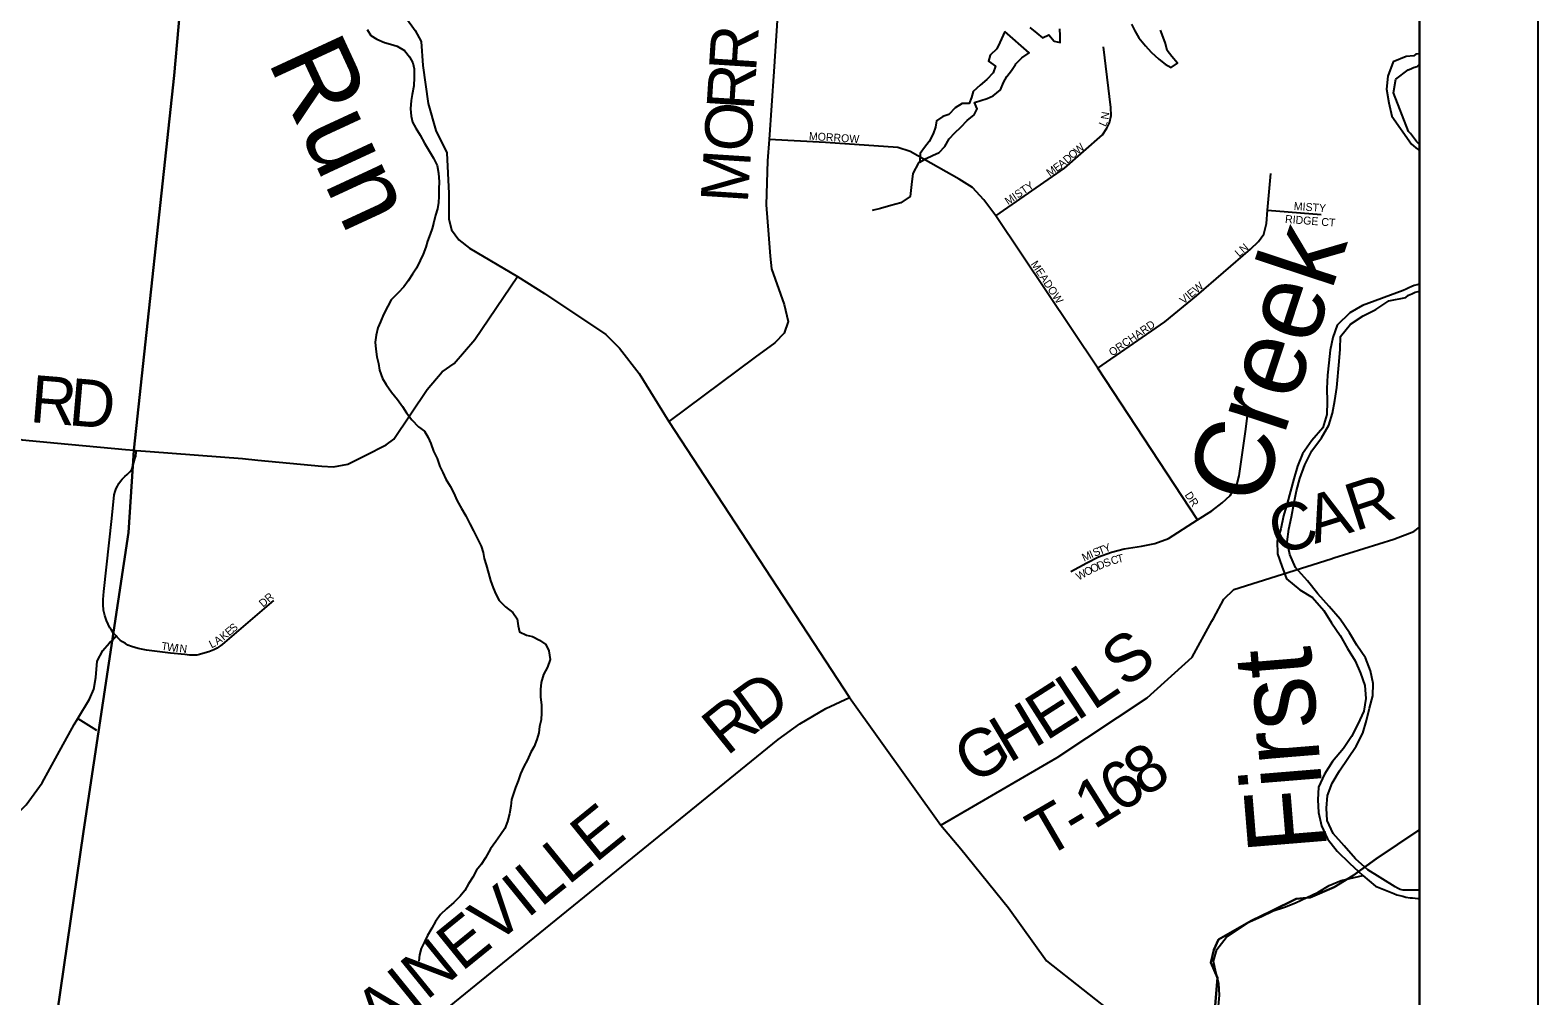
# Model space of a CAD drawing. Extents: x 0 to 34, y -4 to 22.
# Drawn here: x 7.725 to 9, y 14.851 to 15.668 of the extents above; entities that cross this region are included whole.
import ezdxf

# ---------------------------------------------------------------- set-up
doc = ezdxf.new("R2010")
doc.units = 0
for name, color, linetype in [('GM_X_County_Road', 7, 'Continuous'), ('GM_X_County_Road_Text', 7, 'Continuous'), ('GM_X_Minor_Lake', 7, 'Continuous'), ('GM_X_Minor_River', 7, 'Continuous'), ('GM_X_Minor_River_Text', 7, 'Continuous'), ('GM_X_Township', 7, 'Continuous'), ('GM_X_Township_Road', 7, 'Continuous'), ('GM_X_Township_Road_Text', 7, 'Continuous'), ('GM_X_Township_Subdivision', 7, 'Continuous'), ('GM_X_Township_Subdivision_Text', 7, 'Continuous'), ('SH_Data', 7, 'Continuous'), ('SN_P_Text', 7, 'Continuous')]:
    doc.layers.add(name, color=color, linetype=linetype)

msp = doc.modelspace()

# ---------------------------------------------------------------- linework, layer by layer
at = {"layer": 'GM_X_County_Road'}
for points in [[(8.0173, 15.7141), (8.0505, 15.668), (8.0555, 15.6587), (8.057, 15.6384), (8.0615, 15.6063), (8.0679, 15.5834), (8.0771, 15.5644), (8.079, 15.5301), (8.0789, 15.5087), (8.0811, 15.4993), (8.0874, 15.4908), (8.0965, 15.4837), (8.137, 15.46), (8.1598, 15.4455), (8.2116, 15.4109), (8.2233, 15.3992), (8.2398, 15.3777), (8.2649, 15.3373)], [(8.3588, 15.711), (8.3537, 15.6333), (8.3498, 15.5756), (8.3485, 15.5576), (8.3474, 15.5205), (8.3493, 15.4955), (8.3507, 15.4772), (8.3518, 15.4663), (8.3625, 15.4361), (8.366, 15.4219), (8.3625, 15.412), (8.3547, 15.4037), (8.3379, 15.3917), (8.2649, 15.3373)], [(8.2649, 15.3373), (8.4177, 15.1037), (8.4949, 14.9957), (8.5119, 14.9757), (8.5524, 14.9258), (8.5844, 14.8809), (8.6458, 14.8325), (8.7276, 14.7769)], [(7.7213, 14.589), (7.7418, 14.5871), (7.7622, 14.5878), (7.773, 14.5936), (8.3575, 15.0682), (8.3759, 15.0816), (8.3979, 15.0945), (8.4177, 15.1037)]]:
    msp.add_lwpolyline(points, dxfattribs=at)
at = {"layer": 'GM_X_Minor_Lake'}
for points in [[(8.6562, 15.6733), (8.6591, 15.6676), (8.6624, 15.6617), (8.6682, 15.6549), (8.6729, 15.6495), (8.6793, 15.6438), (8.6848, 15.6394), (8.6898, 15.6366), (8.6953, 15.6403), (8.6903, 15.646), (8.6866, 15.6511), (8.6851, 15.6568), (8.6831, 15.6624), (8.6807, 15.6683)], [(8.5491, 15.6672), (8.545, 15.6577), (8.5425, 15.6524), (8.5367, 15.6471), (8.5353, 15.642), (8.5414, 15.6377), (8.5392, 15.6321), (8.534, 15.6266), (8.5283, 15.6218), (8.5223, 15.6163), (8.5209, 15.6113), (8.5189, 15.6062), (8.5131, 15.6063), (8.5071, 15.6024), (8.5019, 15.5969), (8.4968, 15.5951), (8.4914, 15.5914), (8.4905, 15.5861), (8.4886, 15.5805), (8.4852, 15.5741), (8.4811, 15.5691), (8.4776, 15.5638), (8.4772, 15.5566), (8.4826, 15.5597), (8.488, 15.5623), (8.4936, 15.5647), (8.4985, 15.5699), (8.5021, 15.5763), (8.5068, 15.5813), (8.5119, 15.5863), (8.5174, 15.5918), (8.5233, 15.5965), (8.5258, 15.6018), (8.5235, 15.6069), (8.5289, 15.6087), (8.5343, 15.6103), (8.5394, 15.6126), (8.5454, 15.6178), (8.5481, 15.6239), (8.5509, 15.629), (8.5547, 15.634), (8.5583, 15.6393), (8.5586, 15.6396)], [(8.5586, 15.6396), (8.5635, 15.6448), (8.5697, 15.649), (8.5491, 15.6672)], [(8.5703, 15.6706), (8.5761, 15.6657), (8.5811, 15.6616), (8.5865, 15.6642), (8.591, 15.6588), (8.596, 15.6577), (8.5961, 15.6635), (8.5957, 15.6694)]]:
    msp.add_lwpolyline(points, dxfattribs=at)
at = {"layer": 'GM_X_Minor_River'}
for points in [[(8.0099, 15.6689), (8.013, 15.6637), (8.0181, 15.6605), (8.0244, 15.6579), (8.0295, 15.6565), (8.0353, 15.6548), (8.0414, 15.651), (8.0456, 15.6458), (8.0485, 15.6407), (8.0495, 15.6354), (8.0496, 15.6281), (8.0492, 15.6212), (8.048, 15.6137), (8.0469, 15.6087), (8.0465, 15.6017), (8.0469, 15.5956), (8.0482, 15.5905), (8.051, 15.5853), (8.0547, 15.5794), (8.0583, 15.5727), (8.0617, 15.567), (8.0659, 15.56), (8.069, 15.5538), (8.0702, 15.5473), (8.0706, 15.5398), (8.0705, 15.534), (8.0704, 15.5276), (8.0701, 15.5225), (8.0692, 15.5171), (8.0677, 15.5118)], [(8.9, 15.6483), (8.8998, 15.6482), (8.8969, 15.648), (8.8951, 15.6465), (8.8885, 15.646)], [(8.8885, 15.646), (8.8777, 15.6414), (8.873, 15.6294), (8.872, 15.6182), (8.8739, 15.6067), (8.8764, 15.5954), (8.893, 15.5718)], [(8.8906, 15.5826), (8.8778, 15.6152), (8.8799, 15.6269), (8.8903, 15.6348)], [(8.8903, 15.6348), (8.8925, 15.6355), (8.8949, 15.6365), (8.8979, 15.6375), (8.9, 15.6395)], [(8.9, 15.5714), (8.8997, 15.5717), (8.8974, 15.5741), (8.8956, 15.5763), (8.894, 15.5785), (8.8922, 15.5807), (8.8906, 15.5826)], [(8.893, 15.5718), (8.8949, 15.5705), (8.8967, 15.5688), (8.8988, 15.5674), (8.9, 15.5665)], [(8.4772, 15.5566), (8.476, 15.5559), (8.4714, 15.5469), (8.4701, 15.5376), (8.4691, 15.5275), (8.4612, 15.5223), (8.4528, 15.5198), (8.4439, 15.5174), (8.4369, 15.5157)], [(8.0677, 15.5118), (8.0663, 15.5057), (8.0649, 15.5006), (8.0632, 15.4956), (8.0609, 15.4897), (8.0595, 15.4847), (8.0573, 15.4788), (8.0545, 15.4733), (8.0515, 15.4669), (8.0482, 15.4619), (8.0446, 15.4563), (8.0408, 15.451), (8.0359, 15.446), (8.0302, 15.44), (8.0274, 15.4347), (8.0235, 15.4278), (8.021, 15.4214), (8.0188, 15.4164), (8.0174, 15.4102), (8.0167, 15.4044), (8.0172, 15.3985), (8.0181, 15.392), (8.0194, 15.3864), (8.0201, 15.3805), (8.0229, 15.3735), (8.0258, 15.3684), (8.0305, 15.3619), (8.0355, 15.3557), (8.0396, 15.35), (8.043, 15.3446), (8.0477, 15.3386), (8.0533, 15.3327), (8.0583, 15.3291), (8.0614, 15.3237), (8.0637, 15.3186), (8.066, 15.3121), (8.0689, 15.3059), (8.0714, 15.2992), (8.0738, 15.2941), (8.0763, 15.2885), (8.08, 15.2825), (8.0828, 15.2771), (8.0859, 15.2701), (8.0896, 15.2636), (8.0932, 15.2574), (8.0966, 15.2507), (8.0997, 15.2448), (8.1038, 15.2369), (8.1062, 15.2318), (8.1079, 15.2265), (8.1089, 15.2214), (8.1104, 15.216), (8.1125, 15.209), (8.1142, 15.2028), (8.1163, 15.1966), (8.1186, 15.1913), (8.1214, 15.1859), (8.1267, 15.1804), (8.1331, 15.1758), (8.1367, 15.1704), (8.1374, 15.1645), (8.1387, 15.1594), (8.1445, 15.1566), (8.1496, 15.1555), (8.1557, 15.1522), (8.161, 15.1486), (8.1635, 15.1432), (8.1645, 15.136), (8.1622, 15.1293), (8.1589, 15.1232), (8.157, 15.1166), (8.1563, 15.1105), (8.1565, 15.104), (8.1574, 15.0976), (8.1573, 15.0907), (8.157, 15.085), (8.1555, 15.0792), (8.1549, 15.0739), (8.1532, 15.0683), (8.151, 15.0624), (8.1482, 15.0574), (8.1454, 15.051), (8.1424, 15.0454), (8.1394, 15.0391), (8.1374, 15.0332), (8.1352, 15.0276), (8.1337, 15.0226), (8.132, 15.0175), (8.1312, 15.0119), (8.1302, 15.0053), (8.1285, 14.9989), (8.1263, 14.993), (8.1225, 14.9877), (8.1186, 14.9819), (8.114, 14.9758), (8.1098, 14.9682), (8.1063, 14.9626), (8.1024, 14.9576), (8.0991, 14.9518), (8.0956, 14.9462), (8.0923, 14.9406)], [(8.8862, 15.4481), (8.8518, 15.4354), (8.841, 15.4292), (8.8304, 15.4187), (8.8267, 15.4083), (8.8244, 15.3976), (8.8232, 15.3867), (8.8222, 15.3763), (8.8215, 15.3651), (8.8218, 15.3541), (8.8214, 15.3431), (8.818, 15.332), (8.8087, 15.3212), (8.8008, 15.3098), (8.7966, 15.2994), (8.7935, 15.2888), (8.7909, 15.2784), (8.788, 15.268), (8.7849, 15.2574), (8.7826, 15.2464), (8.7795, 15.2361), (8.7798, 15.2254), (8.7834, 15.2149), (8.7875, 15.2041), (8.7986, 15.1949), (8.8095, 15.1883), (8.8189, 15.1774), (8.8254, 15.1669), (8.8327, 15.1561), (8.839, 15.1453), (8.8455, 15.1348), (8.8499, 15.1243), (8.8537, 15.1138), (8.8546, 15.1028), (8.8528, 15.0921), (8.8478, 15.0813), (8.8423, 15.0709), (8.8357, 15.0606), (8.8264, 15.0495), (8.8196, 15.0389), (8.8146, 15.028), (8.8139, 15.0171), (8.8145, 15.0064), (8.817, 14.9951), (8.8222, 14.9843), (8.8303, 14.9738), (8.8408, 14.9637), (8.8521, 14.9531), (8.8627, 14.9441), (8.8781, 14.9379)], [(8.9, 15.4534), (8.8978, 15.4529), (8.8954, 15.4522), (8.8935, 15.4514), (8.8908, 15.4502), (8.8886, 15.4492), (8.8862, 15.4481)], [(8.8882, 15.4422), (8.8907, 15.444), (8.8934, 15.4453), (8.8963, 15.4466), (8.8988, 15.4473), (8.9, 15.4474)], [(8.8793, 14.9437), (8.8562, 14.9579), (8.8457, 14.9674), (8.8362, 14.9782), (8.827, 14.9888), (8.8219, 14.9996), (8.8212, 15.0103), (8.8222, 15.021), (8.8261, 15.0313), (8.8322, 15.0417), (8.8393, 15.0522), (8.8462, 15.0626), (8.852, 15.0737), (8.8551, 15.0843), (8.8577, 15.0947), (8.8605, 15.1051), (8.8607, 15.1155), (8.8585, 15.1263), (8.8541, 15.1373), (8.847, 15.1481), (8.8408, 15.1586), (8.8327, 15.17), (8.8235, 15.1808), (8.8138, 15.1914), (8.8051, 15.2025), (8.7949, 15.2136), (8.7903, 15.2247), (8.788, 15.2354), (8.7893, 15.2461), (8.7916, 15.2565), (8.7936, 15.2674), (8.796, 15.2786), (8.7988, 15.289), (8.803, 15.3007), (8.8088, 15.3123), (8.817, 15.3234), (8.8231, 15.334), (8.8262, 15.3444), (8.8283, 15.3551), (8.8301, 15.366), (8.832, 15.3879), (8.8327, 15.3983), (8.8332, 15.409), (8.8414, 15.4196), (8.8522, 15.4266), (8.863, 15.432), (8.8741, 15.4394), (8.8882, 15.4422)], [(8.7299, 14.8428), (8.7306, 14.8521), (8.7303, 14.862), (8.7275, 14.8714), (8.7258, 14.8808), (8.7286, 14.8907), (8.7365, 14.9007), (8.7465, 14.9075), (8.7568, 14.9143), (8.7662, 14.9184), (8.7762, 14.9233), (8.7856, 14.9264), (8.795, 14.93), (8.8047, 14.9346), (8.8142, 14.939), (8.8236, 14.9448), (8.8336, 14.9489), (8.8521, 14.9531)], [(8.0923, 14.9406), (8.0884, 14.9356), (8.083, 14.9304), (8.077, 14.9251), (8.0719, 14.9201), (8.0675, 14.9143), (8.0645, 14.9087), (8.0609, 14.9024), (8.0584, 14.8971), (8.0556, 14.8915), (8.0542, 14.8862), (8.0536, 14.8808)], [(8.8781, 14.9379), (8.8808, 14.9368), (8.8834, 14.9362), (8.8858, 14.9356), (8.8882, 14.935), (8.892, 14.9343), (8.8941, 14.9343), (8.8963, 14.934), (8.8984, 14.9337), (8.9, 14.9335)], [(8.9, 14.9408), (8.8988, 14.9409), (8.8967, 14.9407), (8.8948, 14.9407), (8.8929, 14.9407), (8.8908, 14.9408), (8.8887, 14.9408), (8.886, 14.9409), (8.8836, 14.9415), (8.8812, 14.9426), (8.8793, 14.9437)]]:
    msp.add_lwpolyline(points, dxfattribs=at)
at = {"layer": 'GM_X_Township'}
for points in [[(8.7269, 14.8398), (8.729, 14.8668), (8.7233, 14.8795), (8.726, 14.8904), (8.7299, 14.8992), (8.7574, 14.9149), (8.7743, 14.9231), (8.7955, 14.9334), (8.8073, 14.9346), (8.8276, 14.9434), (8.8439, 14.9533), (8.8632, 14.9673), (8.8993, 14.9917), (8.9, 14.9923), (8.9, 19.071)], [(3.8794, 14.1), (7.6703, 14.1), (7.7118, 14.5899), (7.7699, 14.9905), (7.8078, 15.2433), (7.8116, 15.2993), (7.8125, 15.3129), (7.8465, 15.6298), (7.8833, 16.0418)], [(7.8833, 16.0418), (7.8465, 15.6298), (7.8125, 15.3129), (7.8116, 15.2993), (7.8078, 15.2433), (7.7699, 14.9905), (7.7118, 14.5899)], [(8.9, 14.1), (8.9, 14.9923), (8.8993, 14.9917), (8.8632, 14.9673), (8.8439, 14.9533), (8.8276, 14.9434), (8.8073, 14.9346), (8.7955, 14.9334), (8.7743, 14.9231), (8.7574, 14.9149), (8.7299, 14.8992), (8.726, 14.8904), (8.7233, 14.8795), (8.729, 14.8668), (8.7269, 14.8398)]]:
    msp.add_lwpolyline(points, dxfattribs=at)
at = {"layer": 'GM_X_Township_Road'}
for points in [[(7.9172, 15.3046), (7.9715, 15.2994), (7.9813, 15.299), (7.9934, 15.3012), (8.0081, 15.3086), (8.0259, 15.3175), (8.0323, 15.3224), (8.0606, 15.3642), (8.0732, 15.3791), (8.0834, 15.3863), (8.1009, 15.4065), (8.137, 15.46)], [(7.248, 15.4237), (7.3198, 15.4102), (7.4966, 15.373), (7.6114, 15.3461), (7.6877, 15.3284), (7.7181, 15.3218), (7.7478, 15.3188), (7.8053, 15.3135)], [(7.8053, 15.3135), (7.8125, 15.3129), (7.8143, 15.3128), (7.8263, 15.3119)], [(7.8263, 15.3119), (7.9044, 15.3058), (7.9172, 15.3046)], [(8.8275, 15.2218), (8.8782, 15.2377), (8.8951, 15.2443), (8.9, 15.2478)], [(8.7256, 15.1707), (8.7345, 15.1869), (8.7429, 15.195), (8.8253, 15.221), (8.8275, 15.2218)], [(8.4949, 14.9957), (8.5933, 15.0529), (8.6696, 15.1034), (8.7076, 15.138), (8.7243, 15.1683), (8.7256, 15.1707)]]:
    msp.add_lwpolyline(points, dxfattribs=at)
at = {"layer": 'GM_X_Township_Subdivision'}
for points in [[(8.5415, 15.5113), (8.5996, 15.5515), (8.6317, 15.5797), (8.6354, 15.5853), (8.6378, 15.5899), (8.639, 15.596), (8.6388, 15.6028), (8.6325, 15.6541)], [(8.7122, 15.2541), (8.6279, 15.3823), (8.5415, 15.5113), (8.5314, 15.5247), (8.5218, 15.5351), (8.5106, 15.5422), (8.4692, 15.5656), (8.4588, 15.5689), (8.3974, 15.5731), (8.3498, 15.5756)], [(8.6279, 15.3823), (8.6845, 15.4216), (8.7113, 15.4435), (8.757, 15.4829), (8.7638, 15.4895), (8.7682, 15.4958), (8.7704, 15.5048), (8.7714, 15.5159), (8.7742, 15.5469)], [(8.7714, 15.5159), (8.8166, 15.5124)], [(8.605, 15.2103), (8.6186, 15.2178), (8.6283, 15.2227), (8.6395, 15.2266), (8.6502, 15.2295), (8.6648, 15.2319), (8.676, 15.2341), (8.6877, 15.2382), (8.7122, 15.2541), (8.7242, 15.2616), (8.7329, 15.2684), (8.7397, 15.2747), (8.7456, 15.2849), (8.7475, 15.2913), (8.7528, 15.3289), (8.7543, 15.3421)], [(7.8116, 15.2993), (7.8133, 15.3055), (7.814, 15.3079), (7.8143, 15.3113), (7.8143, 15.3128)], [(7.7951, 15.1584), (7.7933, 15.1613), (7.7922, 15.1628), (7.7906, 15.1658), (7.7892, 15.1689), (7.7879, 15.173), (7.7868, 15.1775), (7.7864, 15.1824), (7.7866, 15.1867), (7.7871, 15.1933), (7.7937, 15.2553), (7.7959, 15.2753), (7.7968, 15.278), (7.7976, 15.2805), (7.7986, 15.2826), (7.7998, 15.2847), (7.8013, 15.2867), (7.8027, 15.2884), (7.8049, 15.2906), (7.8068, 15.2925), (7.8091, 15.2947), (7.8107, 15.2967), (7.8116, 15.2993)], [(7.9306, 15.1858), (7.8873, 15.1487), (7.8859, 15.1477), (7.8844, 15.1466), (7.8828, 15.1454), (7.88, 15.144), (7.8759, 15.1424), (7.8727, 15.1415), (7.8679, 15.1401), (7.8656, 15.1397), (7.8632, 15.1397), (7.8596, 15.1397), (7.8556, 15.1401), (7.8434, 15.1414), (7.8231, 15.1439), (7.816, 15.1453), (7.8106, 15.1469), (7.8075, 15.148), (7.8053, 15.1494), (7.803, 15.1509), (7.801, 15.1523), (7.7983, 15.1549), (7.7975, 15.1559), (7.7966, 15.1568), (7.7951, 15.1584)], [(7.5588, 14.9904), (7.6124, 14.9886), (7.6672, 14.9875), (7.6799, 14.9899), (7.6943, 14.9939), (7.7121, 15.0035), (7.7214, 15.013), (7.735, 15.0317), (7.748, 15.0553), (7.7621, 15.0809), (7.7652, 15.086), (7.7749, 15.1024), (7.7786, 15.1107), (7.7802, 15.1208), (7.7815, 15.1346), (7.7861, 15.1435), (7.788, 15.1456), (7.7899, 15.1477), (7.792, 15.1501), (7.7941, 15.1519)], [(7.7941, 15.1519), (7.7975, 15.1559)], [(7.7652, 15.086), (7.781, 15.0761)]]:
    msp.add_lwpolyline(points, dxfattribs=at)
at = {"layer": 'SH_Data'}
for p, q in [((9, 21), (9, 14)), ((8.9, 20.9), (8.9, 14.1))]:
    msp.add_line(p, q, dxfattribs=at)
at = {"layer": 'SN_P_Text'}
msp.add_lwpolyline([(8.9, 14.1), (8.9, 20.9), (2.1, 20.9), (2.1, 14.1)], close=True, dxfattribs=at)

# ---------------------------------------------------------------- texts
at = {"layer": 'GM_X_County_Road_Text'}
for s, rotation, p in [('R', 86.3553, (8.3387, 15.6325)), ('R', 86.3521, (8.3367, 15.5997)), ('O', 86.3538, (8.3344, 15.5646)), ('M', 86.3527, (8.3317, 15.5212)), ('D', 36.3482, (8.3393, 15.074)), ('R', 38.8006, (8.3141, 15.0537)), ('FOSTERS-MAINEVILLE', 39.0783, (7.7761, 14.6166))]:
    msp.add_text(s, height=0.04, rotation=rotation, dxfattribs=at).set_placement(p)
at = {"layer": 'GM_X_Minor_River_Text'}
for s, rotation, p in [('Run', 294.8367, (7.9253, 15.6423)), ('Creek', 71.7417, (8.7649, 15.2633)), ('First', 94.6723, (8.8219, 14.9753))]:
    msp.add_text(s, height=0.06667, rotation=rotation, dxfattribs=at).set_placement(p)
at = {"layer": 'GM_X_Township_Road_Text'}
for s, rotation, p in [('R', 355.3699, (7.7238, 15.3368)), ('D', 355.08, (7.7565, 15.3342)), ('R', 17.9544, (8.8454, 15.2442)), ('A', 17.3586, (8.8114, 15.2336)), ('C', 17.3475, (8.78, 15.2238)), ('S', 38.3301, (8.6514, 15.111)), ('L', 33.8615, (8.6238, 15.0923)), ('E', 32.5812, (8.5841, 15.0666)), ('I', 33.4753, (8.6098, 15.0831)), ('H', 30.9121, (8.5528, 15.0478)), ('G', 30.2591, (8.5219, 15.0298)), ('8', 33.393, (8.6669, 15.0187)), ('6', 33.0544, (8.6461, 15.0051)), ('1', 32.0905, (8.6246, 14.9916)), ('T', 30.2185, (8.5834, 14.9673)), ('-', 31.1379, (8.6099, 14.9827))]:
    msp.add_text(s, height=0.04, rotation=rotation, dxfattribs=at).set_placement(p)
at = {"layer": 'GM_X_Township_Subdivision_Text'}
for s, rotation, p in [('N', 81.4249, (8.6368, 15.5923)), ('L', 66.0264, (8.6344, 15.5861)), ('MORROW', 356.4228, (8.3833, 15.5754)), ('W', 41.0736, (8.6109, 15.5627)), ('A', 38.7854, (8.5972, 15.5511)), ('D', 41.0022, (8.602, 15.555)), ('O', 41.0817, (8.6064, 15.5588)), ('M', 35.0592, (8.5872, 15.5441)), ('E', 35.0934, (8.593, 15.5481)), ('MISTY', 34.4414, (8.552, 15.52)), ('MISTY', 356.0112, (8.7934, 15.5162)), ('RIDGE CT', 355.5318, (8.786, 15.5053)), ('LN', 40.9166, (8.7473, 15.476)), ('MEADOW', 303.4764, (8.5708, 15.4704)), ('VIEW', 39.8086, (8.7004, 15.4361)), ('ORCHARD', 34.853, (8.64, 15.3921)), ('DR', 303.6867, (8.701, 15.2751)), ('M', 24.1696, (8.6162, 15.2186)), ('I', 24.14, (8.6226, 15.2215)), ('S', 22.603, (8.6252, 15.2227)), ('T', 20.5784, (8.6295, 15.2244)), ('Y', 21.0944, (8.634, 15.2261)), ('O', 27.9143, (8.6183, 15.2063)), ('O', 25.7734, (8.6234, 15.209)), ('D', 23.3966, (8.6286, 15.2115)), ('S', 20.7511, (8.634, 15.2138)), ('C', 16.1155, (8.6399, 15.216)), ('T', 13.3406, (8.6449, 15.2175)), ('W', 28.746, (8.6116, 15.2026)), ('DR', 40.9083, (7.9218, 15.1797)), ('E', 39.7951, (7.893, 15.1554)), ('S', 39.7951, (7.8966, 15.1584)), ('T', 351.9974, (7.8354, 15.1442)), ('W', 352.0126, (7.8401, 15.1435)), ('L', 26.9926, (7.8781, 15.1453)), ('A', 34.4893, (7.8831, 15.1479)), ('K', 39.8222, (7.8885, 15.1516)), ('I', 352.0348, (7.8476, 15.1425)), ('N', 353.1839, (7.8507, 15.1421))]:
    msp.add_text(s, height=0.00667, rotation=rotation, dxfattribs=at).set_placement(p)

doc.saveas('drawing.dxf')
